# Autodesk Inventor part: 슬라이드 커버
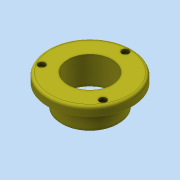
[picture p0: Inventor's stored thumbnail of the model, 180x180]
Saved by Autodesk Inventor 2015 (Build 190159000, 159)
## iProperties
Created: 2015-10
Part Number: 슬라이드 커버
Document SubType Name: Modeling
Designer: mdu
Density: 7.86 g/cm^3
Material: 강철, 연강
Mass: 635.45 g
Surface Area: 238.05 cm^2
Volume: 80.8461 cm^3
Appearance: 밝은 황색
Author: mdu
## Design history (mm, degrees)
sketch "스케치1"
  geometry: C1 r 47.5 at (0, 0); C2 r 32.5 at (0, 0); 1 further point
  constraints: 2 centre point, 2 coincident
  dimensions: "d33" = 95 diameter of C1; "d35" = 65 diameter of C2
extrude "돌출1" new body sketch "스케치1" distance "d0" = 10; taper "d1" = 0 deg
extrude "돌출2" join sketch "스케치1" distance "d2" = 25; taper "d3" = 0 deg
hole "구멍1" diameter "d6" = 50; stored, may be unused: countersink angle "d10" = 90 deg, drill point angle "d12" = 118 deg; dims "d4" = 10, "d5" = 10, "d7" = 6, "d8" = 4, "d9" = 2, "d11" = 8
sketch "스케치2" dims "d36" = 80
  geometry: 4 further points
  constraints: 2 coincident, 2 vertical alignment, 2 other
hole "구멍2" sketch "스케치2" at (0, 40) diameter "d13" = 4.5; stored, may be unused: countersink angle "d17" = 90 deg, drill point angle "d19" = 118 deg; dims "d14" = 6, "d15" = 8, "d16" = 4.4, "d18" = 8
fillet "모깎기1" dims "d23" = 3
chamfer "모따기1" distance "d24" = 1; stored, may be unused: second distance "d25" = 2, angle "d26" = 45 deg
sketch "스케치3"
  geometry: C1 r 25 at (0, 0); C2 r 30 at (0, 0); C3 r 26 at (0, 0) reference; 1 further point
  constraints: 2 centre point, 2 coincident
  dimensions: "d27" = 60 diameter of C2
extrude "돌출3" cut sketch "스케치3" distance "d28" = 3; taper "d29" = 0 deg
chamfer "모따기2" distance "d30" = 1; stored, may be unused: second distance "d31" = 2, angle "d32" = 45 deg
node "솔리드1"
pattern_circular "원형 패턴1" dims angle "d21" = 360 deg
